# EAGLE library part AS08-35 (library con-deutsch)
DEUTSCH Connector
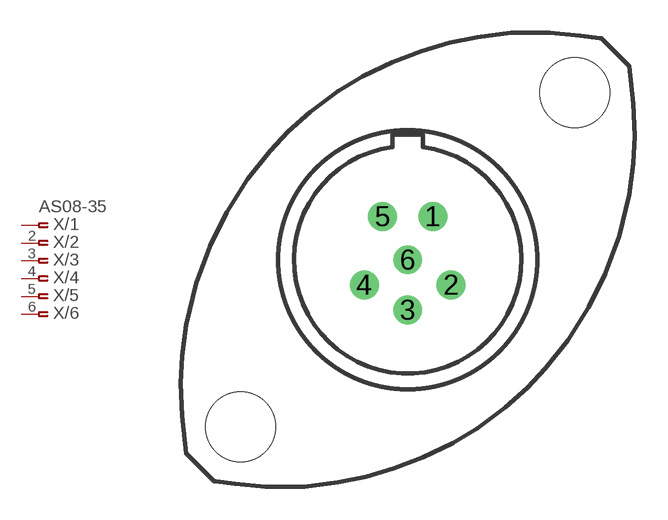
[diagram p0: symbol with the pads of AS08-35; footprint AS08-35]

Designator prefix X; gates /1=PINF_VAL /2=ASPINF /3=ASPINF /4=ASPINF /5=ASPINF /6=ASPINF

## AS08-35 (OC_FARNELL: unknown; OC_NEWARK: unknown)  [AS08-35]
1  /1:1  pas
2  /2:1  pas
3  /3:1  pas
4  /4:1  pas
5  /5:1  pas
6  /6:1  pas

## Footprint AS08-35 (pad centres in mm)
DEUTSCH Connector
drill 0.813 round: 1 1.143,1.981; 2 1.981,-1.143; 3 0,-2.286; 4 -1.981,-1.143; 5 -1.143,1.981; 6 0,0
hole 3.2 at -7.62,-7.62
hole 3.2 at 7.62,7.62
